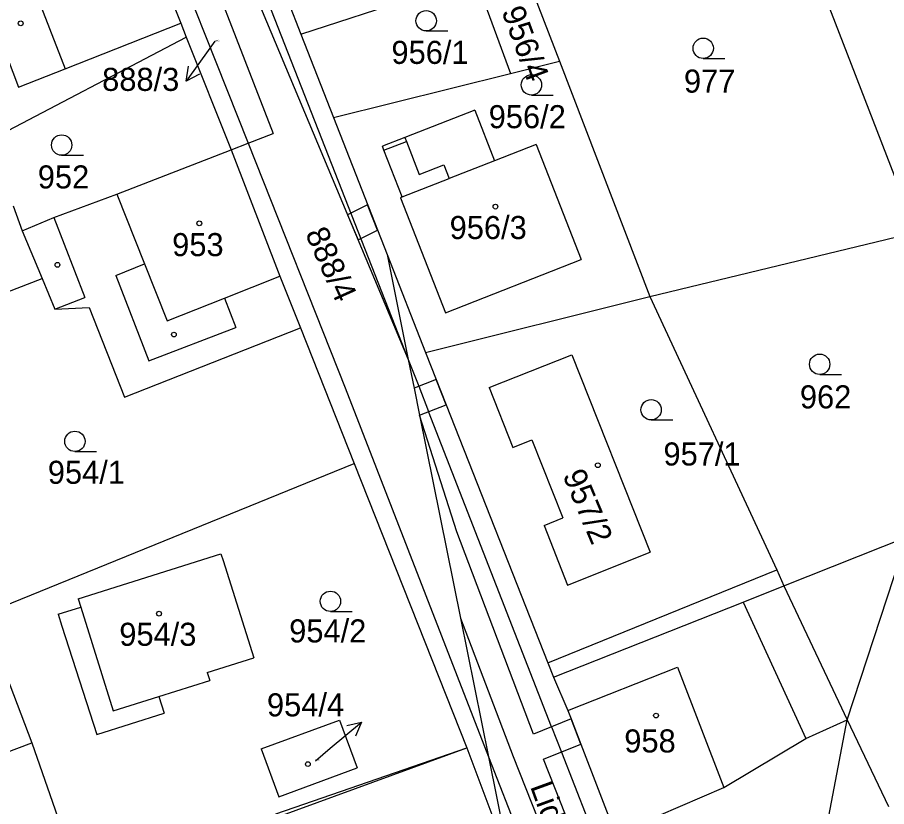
# Model space of a CAD drawing. Extents: x -785744 to -782822, y -1067550 to -1063910.
# Drawn here: x -783681.1 to -783617, y -1065951.9 to -1065893.8 of the extents above; entities that cross this region are included whole.
import ezdxf

# ---------------------------------------------------------------- set-up
doc = ezdxf.new("R2010")
doc.units = 0
for name, color, linetype in [('Hranice parcel', 7, 'Continuous'), ('Parcelní čísla', 7, 'Continuous'), ('Pop_ČP_popisy', 7, 'Continuous'), ('Vnitřní kresba', 7, 'Continuous'), ('Věcná břemena k části', 7, 'Continuous'), ('Značky budov', 7, 'Continuous'), ('Značky kultur', 7, 'Continuous')]:
    doc.layers.add(name, color=color, linetype=linetype)

msp = doc.modelspace()

# ---------------------------------------------------------------- linework, layer by layer
at = {"layer": 'Hranice parcel'}
for p, q in [((-783660.25, -1065895), (-783647.38, -1065890.83)), ((-783647.38, -1065890.83), (-783644.78, -1065897.9)), ((-783644.78, -1065897.9), (-783641.17, -1065897)), ((-783657.84, -1065901.16), (-783644.78, -1065897.9))]:
    msp.add_line(p, q, dxfattribs=at)
for points in [[(-783668.05, -1065881.45), (-783652.32, -1065918.99)], [(-783669.2, -1065884.51), (-783662.28, -1065902.34)], [(-783672.47, -1065885.78), (-783669.1, -1065894.21)], [(-783623.73, -1065886.65), (-783614.87, -1065909.61)], [(-783643.96, -1065889.72), (-783641.17, -1065897)], [(-783661.21, -1065892.55), (-783660.25, -1065895)], [(-783669.1, -1065894.21), (-783668.69, -1065895.24)], [(-783683.35, -1065902.9), (-783668.69, -1065895.24)], [(-783668.69, -1065895.24), (-783665.38, -1065903.54)], [(-783660.25, -1065895), (-783657.84, -1065901.16)], [(-783641.17, -1065897), (-783634.51, -1065914.35)], [(-783647.42, -1065900.62), (-783652.57, -1065902.62)], [(-783647.42, -1065900.62), (-783645.96, -1065904.35)], [(-783657.84, -1065901.16), (-783653.88, -1065911.25)], [(-783664.12, -1065903.05), (-783662.28, -1065902.34)], [(-783665.38, -1065903.54), (-783664.12, -1065903.05)], [(-783652.57, -1065902.62), (-783654.23, -1065903.26)], [(-783642.88, -1065903.14), (-783645.96, -1065904.35)], [(-783642.88, -1065903.14), (-783639.57, -1065911.62)], [(-783673.8, -1065906.8), (-783665.38, -1065903.54)], [(-783665.38, -1065903.54), (-783661.79, -1065912.85)], [(-783654.11, -1065903.55), (-783654.23, -1065903.26)], [(-783652.76, -1065907.01), (-783654.11, -1065903.55)], [(-783678.46, -1065908.52), (-783673.8, -1065906.8)], [(-783652.76, -1065907.01), (-783652.89, -1065907.06)], [(-783652.89, -1065907.06), (-783649.57, -1065915.54)], [(-783681.45, -1065907.66), (-783680.78, -1065909.5)], [(-783680.78, -1065909.5), (-783678.46, -1065908.52)], [(-783680.78, -1065909.5), (-783679.31, -1065913.02)], [(-783634.51, -1065914.35), (-783614.87, -1065909.61)], [(-783653.88, -1065911.25), (-783651.05, -1065918.48)], [(-783653.88, -1065911.25), (-783652.32, -1065918.99)], [(-783649.57, -1065915.54), (-783639.57, -1065911.62)], [(-783661.79, -1065912.85), (-783660.27, -1065916.66)], [(-783682.72, -1065914.32), (-783679.31, -1065913.02)], [(-783679.31, -1065913.02), (-783678.38, -1065915.28)], [(-783651.05, -1065918.48), (-783634.51, -1065914.35)], [(-783634.51, -1065914.35), (-783625.15, -1065934.5)], [(-783678.38, -1065915.28), (-783675.84, -1065915.15)], [(-783675.84, -1065915.15), (-783673.25, -1065921.76)], [(-783673.25, -1065921.76), (-783660.27, -1065916.66)], [(-783660.27, -1065916.66), (-783656.3, -1065926.66)], [(-783651.05, -1065918.48), (-783650.27, -1065920.46)], [(-783652.32, -1065918.99), (-783651.89, -1065921.09)], [(-783646.35, -1065921.06), (-783640.27, -1065918.64)], [(-783640.27, -1065918.64), (-783634.48, -1065933.19)], [(-783650.27, -1065920.46), (-783649.53, -1065922.32)], [(-783651.89, -1065921.09), (-783651.49, -1065923.08)], [(-783646.35, -1065921.06), (-783644.6, -1065925.47)], [(-783649.53, -1065922.32), (-783642.03, -1065941.34)], [(-783651.49, -1065923.08), (-783648.47, -1065938.04)], [(-783644.6, -1065925.47), (-783643.21, -1065924.91)], [(-783643.21, -1065924.91), (-783640.92, -1065930.66)], [(-783683.7, -1065937.77), (-783656.3, -1065926.66)], [(-783656.3, -1065926.66), (-783647.99, -1065947.6)], [(-783642.31, -1065931.21), (-783640.92, -1065930.66)], [(-783642.31, -1065931.21), (-783640.57, -1065935.62)], [(-783619.96, -1065945.55), (-783615.53, -1065932.05)], [(-783676.66, -1065936.63), (-783666.13, -1065933.31)], [(-783666.13, -1065933.31), (-783665.97, -1065933.81)], [(-783640.57, -1065935.62), (-783634.48, -1065933.19)], [(-783665.97, -1065933.81), (-783663.71, -1065940.98)], [(-783642.03, -1065941.34), (-783625.15, -1065934.5)], [(-783627.63, -1065936.86), (-783624.63, -1065935.67)], [(-783624.63, -1065935.67), (-783619.96, -1065945.55)], [(-783676.66, -1065936.63), (-783676.47, -1065937.24)], [(-783641.6, -1065942.41), (-783627.63, -1065936.86)], [(-783683.7, -1065937.77), (-783680.07, -1065947.23)], [(-783678.14, -1065937.76), (-783676.47, -1065937.24)], [(-783678.14, -1065937.76), (-783677.86, -1065938.64)], [(-783648.47, -1065938.04), (-783646.4, -1065948.26)], [(-783677.86, -1065938.64), (-783675.28, -1065946.62)], [(-783667.14, -1065942.06), (-783663.71, -1065940.98)], [(-783642.03, -1065941.34), (-783641.6, -1065942.41)], [(-783667.14, -1065942.06), (-783666.96, -1065942.64)], [(-783670.71, -1065943.82), (-783666.96, -1065942.64)], [(-783641.6, -1065942.41), (-783640.55, -1065944.85)], [(-783670.71, -1065943.82), (-783670.31, -1065945.06)], [(-783640.55, -1065944.85), (-783640.31, -1065945.48)], [(-783675.28, -1065946.62), (-783670.31, -1065945.06)], [(-783640.31, -1065945.48), (-783639.59, -1065947.35)], [(-783663.17, -1065947.69), (-783657.38, -1065945.57)], [(-783657.38, -1065945.57), (-783656.09, -1065949.08)], [(-783624.58, -1065969.81), (-783619.96, -1065945.55)], [(-783623, -1065946.92), (-783619.96, -1065945.55)], [(-783619.96, -1065945.55), (-783616.91, -1065951.92)], [(-783690.9, -1065951.32), (-783680.07, -1065947.23)], [(-783680.07, -1065947.23), (-783677.8, -1065953.8)], [(-783639.59, -1065947.35), (-783637.04, -1065953.96)], [(-783629.05, -1065950.52), (-783623, -1065946.92)], [(-783663.17, -1065947.69), (-783661.87, -1065951.21)], [(-783656.6, -1065950.57), (-783647.99, -1065947.6)], [(-783647.99, -1065947.6), (-783644.83, -1065956.05)], [(-783646.4, -1065948.26), (-783645.12, -1065954.61), (-783644.83, -1065956.05)], [(-783661.87, -1065951.21), (-783656.09, -1065949.08)], [(-783662.09, -1065952.47), (-783656.6, -1065950.57)], [(-783637.04, -1065953.96), (-783629.05, -1065950.52)]]:
    msp.add_lwpolyline(points, dxfattribs=at)
at = {"layer": 'Pop_ČP_popisy'}
for p, q in [((-783666.95, -1065896.04), (-783668.71, -1065898.469)), ((-783658.07, -1065947.64), (-783655.771, -1065945.713))]:
    msp.add_line(p, q, dxfattribs=at)
for points in [[(-783666.58, -1065895.53), (-783666.95, -1065896.04)], [(-783667.718, -1065897.953), (-783668.71, -1065898.469), (-783668.528, -1065897.366)], [(-783656.858, -1065945.972), (-783655.771, -1065945.713), (-783656.216, -1065946.738)], [(-783659.17, -1065948.56), (-783658.07, -1065947.64)]]:
    msp.add_lwpolyline(points, dxfattribs=at)
at = {"layer": 'Vnitřní kresba'}
msp.add_line((-783661.86, -1065952.67), (-783647.99, -1065947.6), dxfattribs=at)
for points in [[(-783665.87, -1065884.44), (-783652.32, -1065918.99)], [(-783671.17, -1065885.28), (-783664.12, -1065903.05)], [(-783680.92, -1065889.06), (-783677.61, -1065897.56)], [(-783684.29, -1065890.44), (-783681.05, -1065898.92)], [(-783677.61, -1065897.56), (-783669.1, -1065894.21)], [(-783681.05, -1065898.92), (-783677.61, -1065897.56)], [(-783664.12, -1065903.05), (-783656.98, -1065921.08)], [(-783654.11, -1065903.55), (-783652.46, -1065902.91)], [(-783652.57, -1065902.62), (-783652.46, -1065902.91)], [(-783652.46, -1065902.91), (-783651.51, -1065905.35)], [(-783645.96, -1065904.35), (-783649.3, -1065905.65)], [(-783651.51, -1065905.35), (-783649.7, -1065904.63)], [(-783649.7, -1065904.63), (-783649.3, -1065905.65)], [(-783652.76, -1065907.01), (-783649.3, -1065905.65)], [(-783673.8, -1065906.8), (-783671.76, -1065911.94)], [(-783678.46, -1065908.52), (-783676.16, -1065914.41)], [(-783673.89, -1065912.79), (-783671.76, -1065911.94)], [(-783671.76, -1065911.94), (-783670.1, -1065916.14)], [(-783673.89, -1065912.79), (-783671.46, -1065919.09)], [(-783665.86, -1065914.46), (-783661.79, -1065912.85)], [(-783678.38, -1065915.28), (-783676.16, -1065914.41)], [(-783670.1, -1065916.14), (-783665.86, -1065914.46)], [(-783665.86, -1065914.46), (-783665.04, -1065916.62)], [(-783671.46, -1065919.09), (-783665.04, -1065916.62)], [(-783652.32, -1065918.99), (-783651.55, -1065920.96), (-783650.82, -1065922.82)], [(-783656.98, -1065921.08), (-783646.4, -1065948.26)], [(-783641.75, -1065946.06), (-783650.82, -1065922.82)], [(-783624.63, -1065935.67), (-783615.53, -1065932.05)], [(-783625.15, -1065934.5), (-783624.63, -1065935.67)], [(-783627.63, -1065936.86), (-783623, -1065946.92)], [(-783676.47, -1065937.24), (-783674.07, -1065944.88)], [(-783640.55, -1065944.85), (-783632.46, -1065941.67)], [(-783632.46, -1065941.67), (-783629.05, -1065950.52)], [(-783674.07, -1065944.88), (-783670.71, -1065943.82)], [(-783641.75, -1065946.06), (-783641.02, -1065947.92), (-783637.18, -1065957.76)], [(-783646.4, -1065948.26), (-783644.12, -1065954.12), (-783643.31, -1065956.22), (-783642.19, -1065959.09)]]:
    msp.add_lwpolyline(points, dxfattribs=at)
at = {"layer": 'Věcná břemena k části'}
for points in [[(-783655.32, -1065907.58), (-783656.79, -1065908.32)], [(-783654.59, -1065909.45), (-783655.32, -1065907.58)], [(-783656.79, -1065908.32), (-783656.02, -1065910.17)], [(-783656.02, -1065910.17), (-783654.59, -1065909.45)], [(-783650.27, -1065920.46), (-783651.89, -1065921.09)], [(-783649.53, -1065922.32), (-783650.27, -1065920.46)], [(-783651.89, -1065921.09), (-783651.49, -1065923.08)], [(-783651.49, -1065923.08), (-783649.53, -1065922.32)], [(-783648.75, -1065931.68), (-783651.49, -1065923.08)], [(-783651.49, -1065923.08), (-783648.47, -1065938.04)], [(-783643.08, -1065946.59), (-783648.75, -1065931.68)], [(-783648.47, -1065938.04), (-783644.58, -1065948.25)], [(-783640.31, -1065945.48), (-783643.08, -1065946.59)], [(-783639.59, -1065947.35), (-783640.31, -1065945.48)], [(-783642.35, -1065948.45), (-783639.59, -1065947.35)], [(-783644.58, -1065948.25), (-783632.73, -1065978.18)], [(-783631.25, -1065976.48), (-783642.35, -1065948.45)]]:
    msp.add_lwpolyline(points, dxfattribs=at)
at = {"layer": 'Značky budov'}
for centre in [(-783680.9, -1065894.21), (-783645.89, -1065907.72), (-783667.73, -1065908.95), (-783678.19, -1065912.01), (-783669.6, -1065917.15), (-783638.34, -1065926.78), (-783670.7, -1065937.72), (-783634.05, -1065945.23), (-783659.72, -1065948.81)]:
    msp.add_circle(centre, 0.175, dxfattribs=at)
at = {"layer": 'Značky kultur'}
for p, q in [((-783651, -1065894.77), (-783649.4, -1065894.77)), ((-783630.57, -1065896.8), (-783628.97, -1065896.8)), ((-783643.24, -1065899.5), (-783641.64, -1065899.5)), ((-783677.88, -1065903.93), (-783676.28, -1065903.93)), ((-783621.98, -1065920.09), (-783620.38, -1065920.09)), ((-783634.41, -1065923.44), (-783632.81, -1065923.44)), ((-783676.9, -1065925.77), (-783675.3, -1065925.77)), ((-783658.06, -1065937.56), (-783656.46, -1065937.56))]:
    msp.add_line(p, q, dxfattribs=at)
for centre in [(-783651, -1065894.02), (-783630.57, -1065896.05), (-783643.24, -1065898.75), (-783677.88, -1065903.18), (-783621.98, -1065919.34), (-783634.41, -1065922.69), (-783676.9, -1065925.02), (-783658.06, -1065936.81)]:
    msp.add_circle(centre, 0.75, dxfattribs=at)

# ---------------------------------------------------------------- texts
at = {"layer": 'Parcelní čísla'}
for s, rotation, p in [('956/4', 290.23335, (-783645.46, -1065893.31)), ('888/4', 294.32556, (-783659.95, -1065909.7)), ('957/2', 292.84254, (-783640.96, -1065927.51))]:
    msp.add_text(s, height=1.7, rotation=rotation, dxfattribs=at).set_placement(p)
for s, height, p in [('888/3', 0.1, (-783666.58, -1065895.53)), ('956/1', 1.7, (-783653.56, -1065897.2)), ('977', 1.7, (-783631.99, -1065899.32)), ('956/2', 1.7, (-783646.39, -1065901.94)), ('952', 1.7, (-783679.64, -1065906.38)), ('956/3', 1.7, (-783649.27, -1065910.11)), ('953', 1.7, (-783669.73, -1065911.37)), ('962', 1.7, (-783623.44, -1065922.59)), ('957/1', 1.7, (-783633.5, -1065926.8)), ('954/1', 1.7, (-783678.9, -1065928.15)), ('954/3', 1.7, (-783673.63, -1065940.09)), ('954/2', 1.7, (-783661.1, -1065939.84)), ('958', 1.7, (-783636.39, -1065947.95)), ('954/4', 0.1, (-783659.17, -1065948.56))]:
    msp.add_text(s, height=height, dxfattribs=at).set_placement(p)
at = {"layer": 'Pop_ČP_popisy'}
for s, p in [('888/3', (-783674.894, -1065899.19)), ('954/4', (-783662.741, -1065945.29))]:
    msp.add_text(s, height=1.7, dxfattribs=at).set_placement(p)
msp.add_text('Lidická', height=1.7, rotation=290.01834, dxfattribs=at).set_placement((-783643.35, -1065950.45))

doc.saveas('drawing.dxf')
